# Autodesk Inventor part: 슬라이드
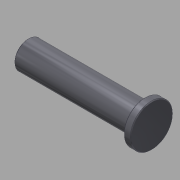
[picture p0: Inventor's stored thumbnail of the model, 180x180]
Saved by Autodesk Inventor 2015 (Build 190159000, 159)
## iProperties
Created: 2015-10
Part Number: 슬라이드
Document SubType Name: Modeling
Designer: mdu
Density: 1 g/cm^3
Material: 강철, 연강
Appearance: 강철 - 광택
Author: mdu
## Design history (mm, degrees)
sketch "스케치1"
  geometry: L1 (-75, 162)-(-75, 58) reference; L2 (-148, 110)-(22, 110); L3 (-148, 110)-(-148, 129); L4 (-148, 129)-(12, 129); L5 (12, 129)-(12, 139); L6 (12, 139)-(22, 139); L7 (22, 139)-(22, 110); 2 further points
  constraints: 12 end point, 3 parallel, 3 perpendicular, 1 midpoint, 1 point on line
  dimensions: "d0" = 58 diameter of L6 L2; "d1" = 38 diameter of L4 L2; "d2" = 10 distance of L5.end L6.end; "d3" = 170 distance of L2.start L2.end; "d4" = 73 distance between parallel lines of L3 L1
revolve "회전1" sketch "스케치1" stored, may be unused: angle "d5" = 90 deg
hole "구멍1" diameter "d11" = 13.376; stored, may be unused: countersink angle "d15" = 90 deg, drill point angle "d17" = 118 deg; dims "d9" = 10, "d10" = 10, "d12" = 22, "d13" = 4, "d14" = 2, "d16" = 25
chamfer "모따기1" distance "d6" = 1; stored, may be unused: second distance "d7" = 2, angle "d8" = 45 deg
node "솔리드1"
node "참조1"
